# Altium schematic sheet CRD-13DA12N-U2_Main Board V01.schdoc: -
size 558 x 431 mm; ENG_APP_DATE: --/--/--; DSN_APP_DATE: --/--/--; CHK_APP_DATE: --/--/--; Date: -; Revision: -; SheetNumber: 1; SheetTotal: 1
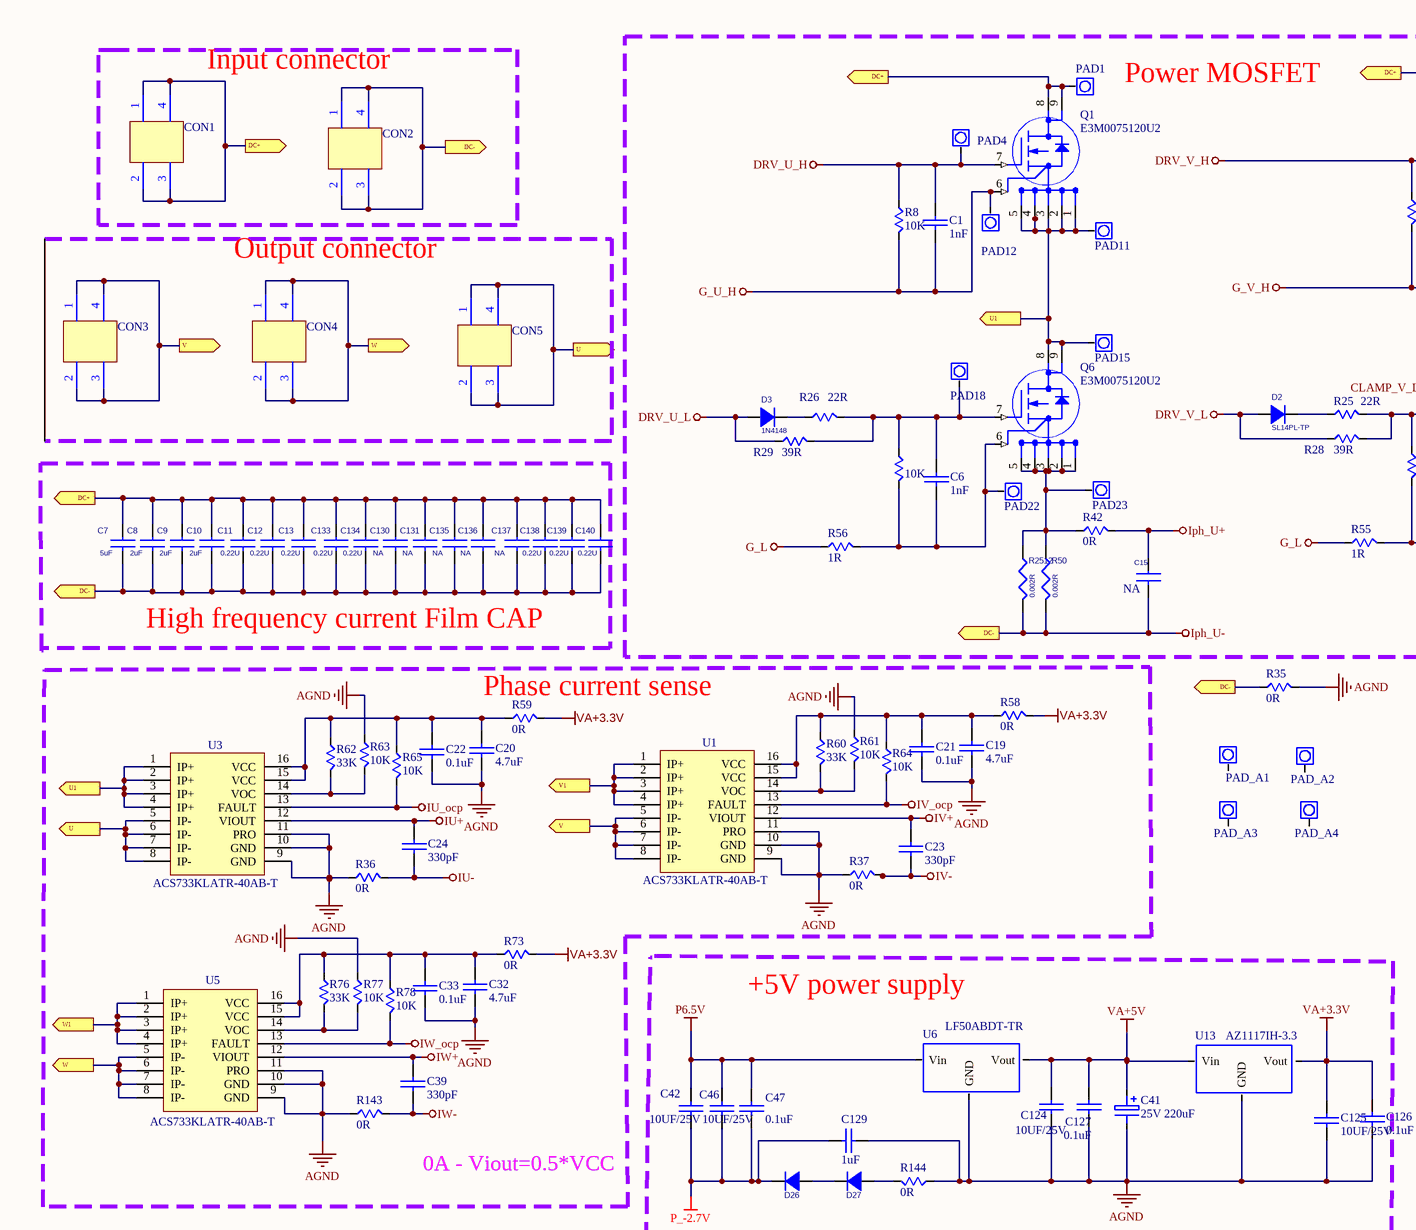
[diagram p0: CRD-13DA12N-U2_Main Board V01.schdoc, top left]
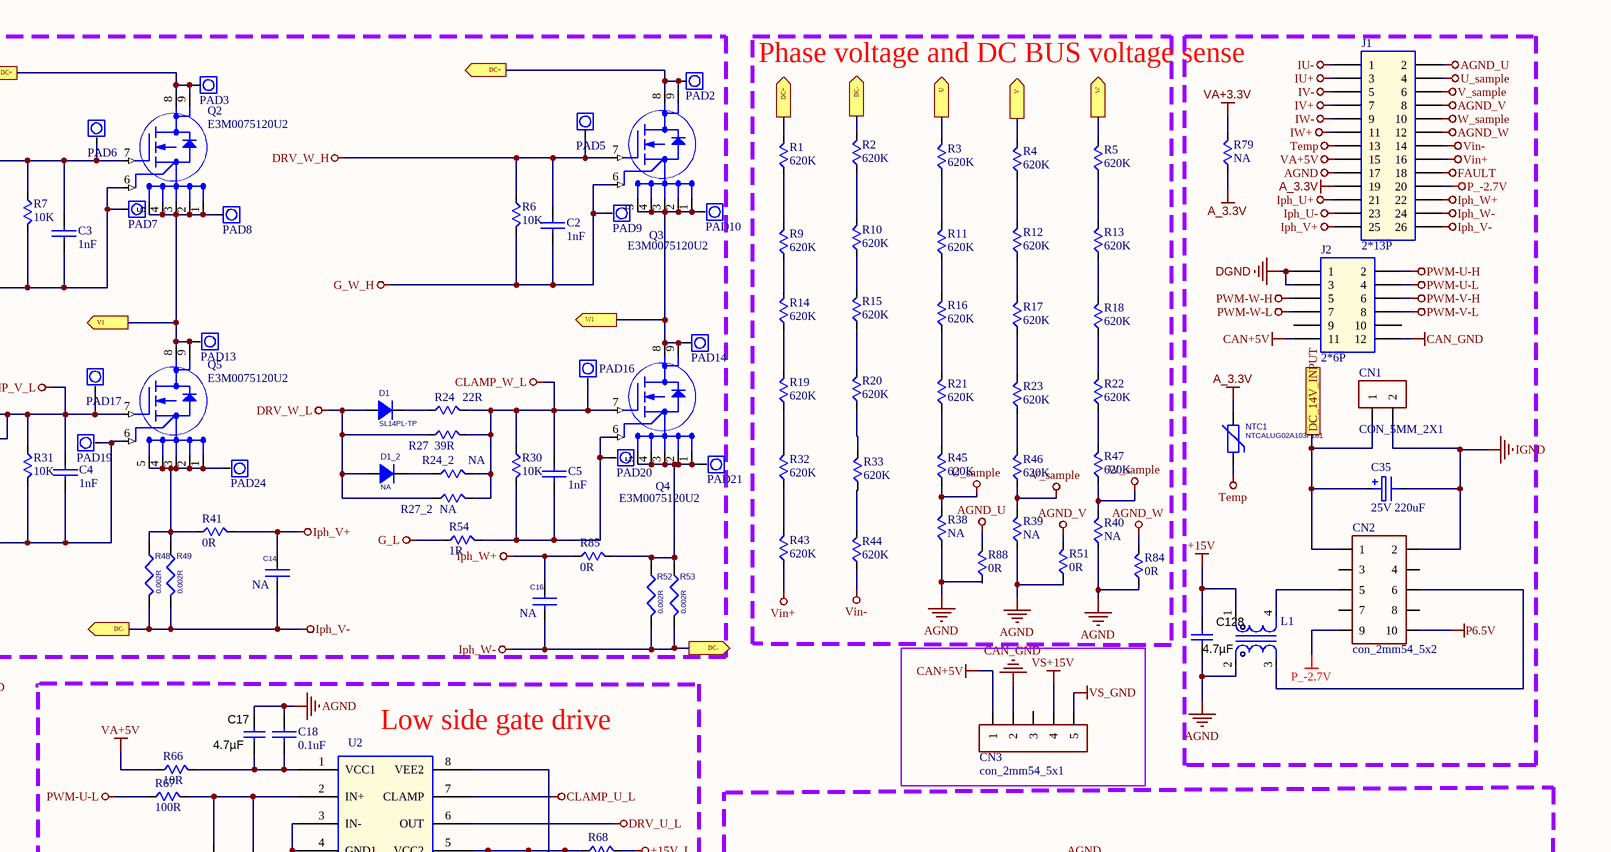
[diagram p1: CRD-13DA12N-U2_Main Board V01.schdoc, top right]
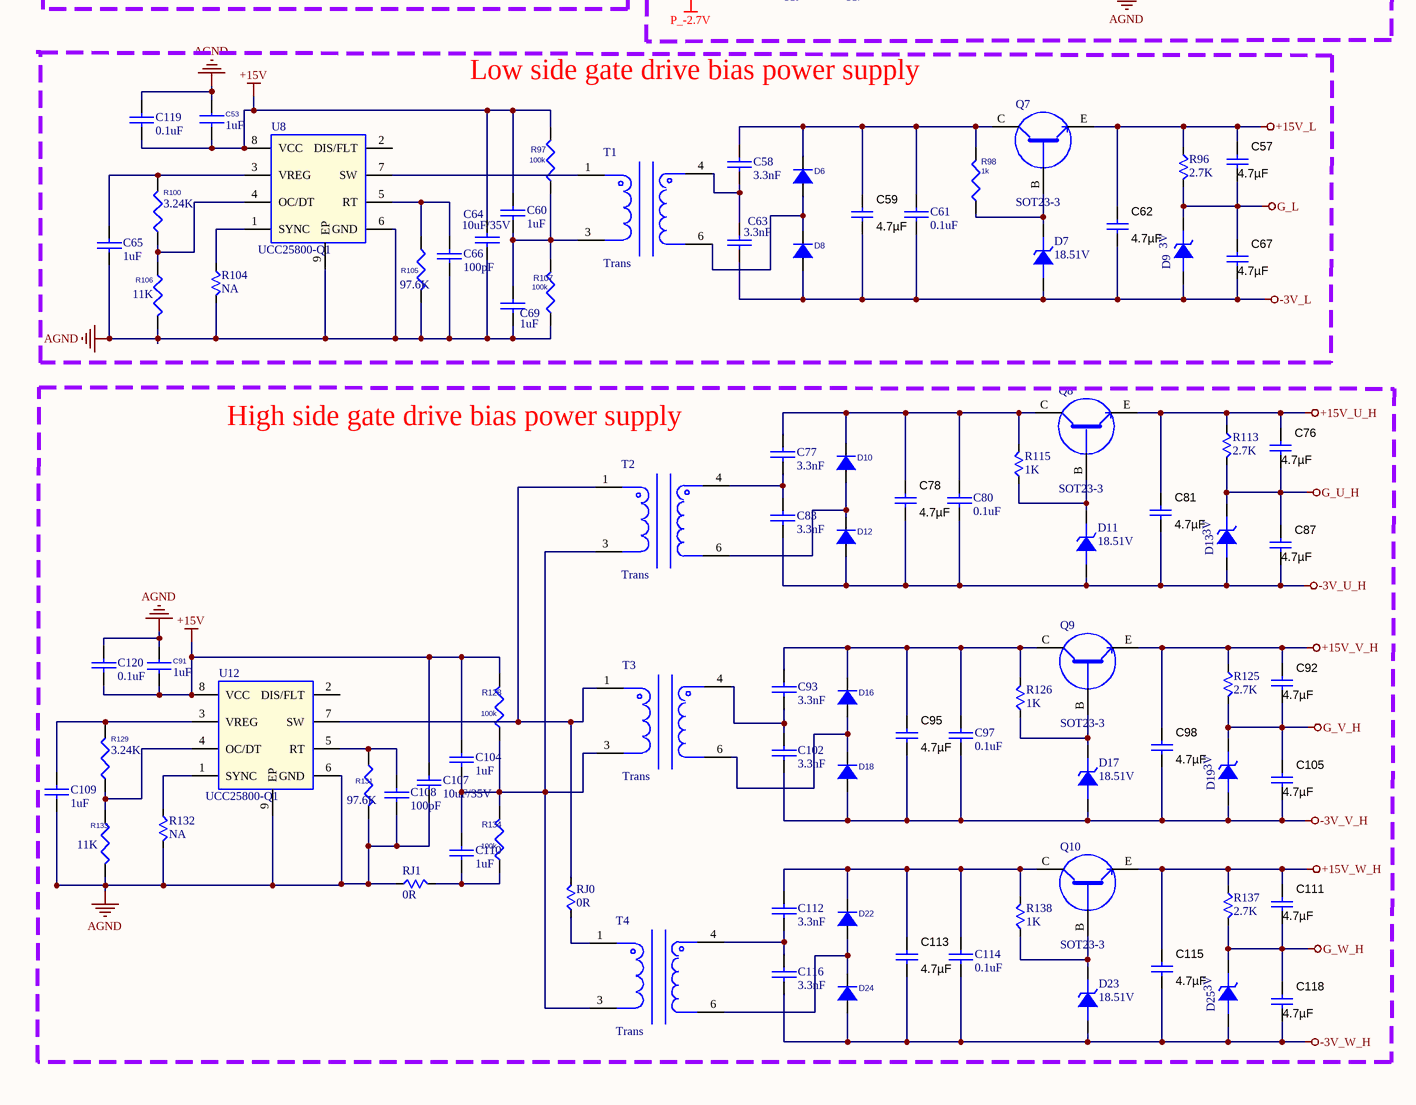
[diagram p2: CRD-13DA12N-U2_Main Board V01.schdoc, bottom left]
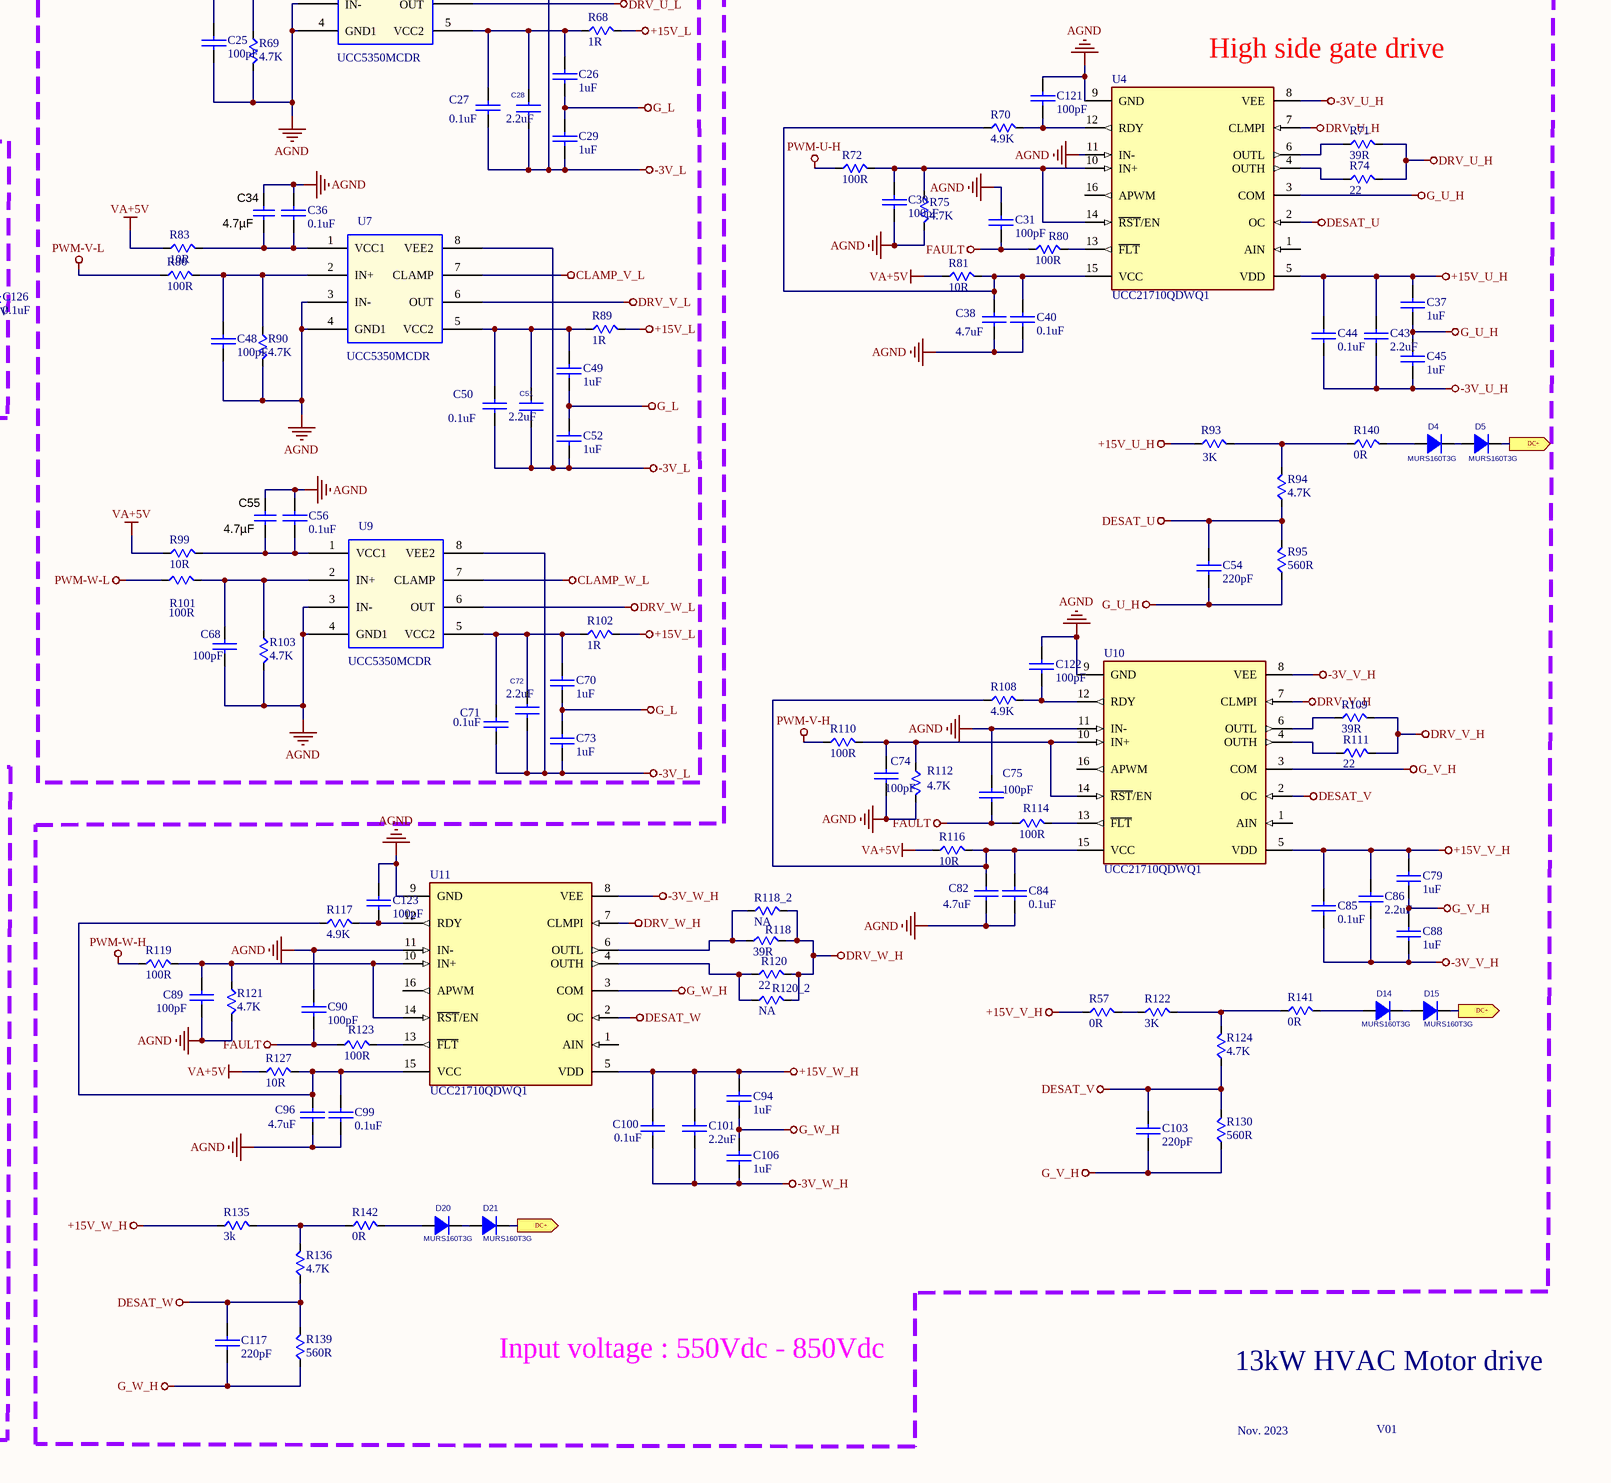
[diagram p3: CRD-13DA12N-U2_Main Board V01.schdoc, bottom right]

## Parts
C1  1nF  [C0603]
C2  1nF  [C0603]
C3  1nF  [C0603]
C4  1nF  [C0603]
C5  1nF  [C0603]
C6  1nF  [C0603]
C7  5uF  [capfilm_31_5x18_5mm]
C8  2uF  [capfilm_31_5x12_5mm]
C9  2uF  [capfilm_31_5x12_5mm]
C10  2uF  [capfilm_31_5x12_5mm]
C11  0.22U  [C2220]
C12  0.22U  [C2220]
C13  0.22U  [C2220]
C14  NA  [0402]
C15  NA  [0402]
C16  NA  [0402]
C17  ValueDisplayed: 4.7µF  [C0603]  (hidden comment: GRT21BR61H475KE13L)
C18  0.1uF  [C0603]
C19  4.7uF  [C0603]
C20  4.7uF  [C0603]
C21  0.1uF  [C0603]
C22  0.1uF  [C0603]
C23  330pF  [C0603]
C24  330pF  [C0603]
C25  100pF  [C0603]
C26  1uF  [C0603]
C27  0.1uF  [C0603]
C28  2.2uF  [C0603]
C29  1uF  [C0603]
C30  100pF  [C0603]
C31  100pF  [C0603]
C32  4.7uF  [C0603]
C33  0.1uF  [C0603]
C34  ValueDisplayed: 4.7µF  [C0603]  (hidden comment: GRT21BR61H475KE13L)
C35  25V 220uF  [ecap_d8p3_5]
C36  0.1uF  [C0603]
C37  1uF  [C0603]
C38  4.7uF  [C0603]
C39  330pF  [C0603]
C40  0.1uF  [C0603]
C41  25V 220uF  [ecap_d8p3_5]
C42  10UF/25V  [C1206]
C43  2.2uF  [C0603]
C44  0.1uF  [C0603]
C45  1uF  [C0603]
C46  10UF/25V  [C1206]
C47  0.1uF  [C0603]
C48  100pF  [C0603]
C49  1uF  [C0603]
C50  0.1uF  [C0603]
C51  2.2uF  [C0603]
C52  1uF  [C0603]
C53  1uF  [C0603]
C54  220pF  [C0603]
C55  ValueDisplayed: 4.7µF  [C0603]  (hidden comment: GRT21BR61H475KE13L)
C56  0.1uF  [C0603]
C57  ValueDisplayed: 4.7µF  [0805_HV]  (hidden comment: GRT21BR61H475KE13L)
C58  3.3nF  [C0805]
C59  ValueDisplayed: 4.7µF  [0805_HV]  (hidden comment: GRT21BR61H475KE13L)
C60  1uF  [C0603]
C61  0.1uF  [C0603]
C62  ValueDisplayed: 4.7µF  [0805_HV]  (hidden comment: GRT21BR61H475KE13L)
C63  3.3nF  [C0805]
C64  10uF/35V  [C1206]
C65  1uF  [C0603]
C66  100pF  [C0603]
C67  ValueDisplayed: 4.7µF  [C0603]  (hidden comment: GRT21BR61H475KE13L)
C68  100pF  [C0603]
C69  1uF  [C0603]
C70  1uF  [C0603]
C71  0.1uF  [C0603]
C72  2.2uF  [C0603]
C73  1uF  [C0603]
C74  100pF  [C0603]
C75  100pF  [C0603]
C76  ValueDisplayed: 4.7µF  [0805_HV]  (hidden comment: GRT21BR61H475KE13L)
C77  3.3nF  [C0805]
C78  ValueDisplayed: 4.7µF  [0805_HV]  (hidden comment: GRT21BR61H475KE13L)
C79  1uF  [C0603]
C80  0.1uF  [C0603]
C81  ValueDisplayed: 4.7µF  [0805_HV]  (hidden comment: GRT21BR61H475KE13L)
C82  4.7uF  [C0603]
C83  3.3nF  [C0805]
C84  0.1uF  [C0603]
C85  0.1uF  [C0603]
C86  2.2uF  [C0603]
C87  ValueDisplayed: 4.7µF  [C0603]  (hidden comment: GRT21BR61H475KE13L)
C88  1uF  [C0603]
C89  100pF  [C0603]
C90  100pF  [C0603]
C91  1uF  [C0603]
C92  ValueDisplayed: 4.7µF  [0805_HV]  (hidden comment: GRT21BR61H475KE13L)
C93  3.3nF  [C0805]
C94  1uF  [C0603]
C95  ValueDisplayed: 4.7µF  [0805_HV]  (hidden comment: GRT21BR61H475KE13L)
C96  4.7uF  [C0603]
C97  0.1uF  [C0603]
C98  ValueDisplayed: 4.7µF  [0805_HV]  (hidden comment: GRT21BR61H475KE13L)
C99  0.1uF  [C0603]
C100  0.1uF  [C0603]
C101  2.2uF  [C0603]
C102  3.3nF  [C0805]
C103  220pF  [C0603]
C104  1uF  [C0603]
C105  ValueDisplayed: 4.7µF  [C0603]  (hidden comment: GRT21BR61H475KE13L)
C106  1uF  [C0603]
C107  10uF/35V  [C1206]
C108  100pF  [C0603]
C109  1uF  [C0603]
C110  1uF  [C0603]
C111  ValueDisplayed: 4.7µF  [0805_HV]  (hidden comment: GRT21BR61H475KE13L)
C112  3.3nF  [C0805]
C113  ValueDisplayed: 4.7µF  [0805_HV]  (hidden comment: GRT21BR61H475KE13L)
C114  0.1uF  [C0603]
C115  ValueDisplayed: 4.7µF  [0805_HV]  (hidden comment: GRT21BR61H475KE13L)
C116  3.3nF  [C0805]
C117  220pF  [C0603]
C118  ValueDisplayed: 4.7µF  [C0603]  (hidden comment: GRT21BR61H475KE13L)
C119  0.1uF  [C0603]
C120  0.1uF  [C0603]
C121  100pF  [C0603]
C122  100pF  [C0603]
C123  100pF  [C0603]
C124  10UF/25V  [C1206]
C125  10UF/25V  [C1206]
C126  0.1uF  [C0603]
C127  0.1uF  [C0603]
C128  ValueDisplayed: 4.7µF  [0805_HV]  (hidden comment: GRT21BR61H475KE13L)
C129  1uF  [C0603]
C130  NA  [C2220]
C131  NA  [C2220]
C133  0.22U  [C2220]
C134  0.22U  [C2220]
C135  NA  [C2220]
C136  NA  [C2220]
C137  NA  [C2220]
C138  0.22U  [C2220]
C139  0.22U  [C2220]
C140  0.22U  [C2220]
CN1  CON_5MM_2X1  [CON_5MM_2X1]
CN2  con_2mm54_5x2  [con_2mm54_5x2]
CN3  con_2mm54_5x1  [con_2mm54_5x1]
CON1  CON  [CON4_500X720-800X800]  (value not drawn)
CON2  CON  [CON4_500X720-800X800]  (value not drawn)
CON3  CON  [CON4_500X720-800X800]  (value not drawn)
CON4  CON  [CON4_500X720-800X800]  (value not drawn)
CON5  CON  [CON4_500X720-800X800]  (value not drawn)
D1  SL14PL-TP  [SOD-123]
D1_2  NA  [SOD-123]
D2  SL14PL-TP  [SOD-123]
D3  1N4148  [SOD-123]
D4  MURS160T3G  [SMB]
D5  MURS160T3G  [SMB]
D6  PMEG6010CEGWJ  [SOD-123]  (value not drawn)
D7  18.51V  [SOD323F]
D8  PMEG6010CEGWJ  [SOD-123]  (value not drawn)
D9  3V  [SMDSOD123]
D10  PMEG6010CEGWJ  [SMDSOD123]  (value not drawn)
D11  18.51V  [SOD323F]
D12  PMEG6010CEGWJ  [SMDSOD123]  (value not drawn)
D13  3V  [SMDSOD123]
D14  MURS160T3G  [SMB]
D15  MURS160T3G  [SMB]
D16  PMEG6010CEGWJ  [SMDSOD123]  (value not drawn)
D17  18.51V  [SOD323F]
D18  PMEG6010CEGWJ  [SMDSOD123]  (value not drawn)
D19  3V  [SMDSOD123]
D20  MURS160T3G  [SMB]
D21  MURS160T3G  [SMB]
D22  PMEG6010CEGWJ  [SMDSOD123]  (value not drawn)
D23  18.51V  [SOD323F]
D24  PMEG6010CEGWJ  [SMDSOD123]  (value not drawn)
D25  3V  [SMDSOD123]
D26  PMEG6010CEGWJ  [SMA]  (value not drawn)
D27  PMEG6010CEGWJ  [SMA]  (value not drawn)
J1  2*13P  [HDR2X13H-254MM-F]
J2  2*6P  [HDR2X6H-254MM-F]
L1  L4_550X1050-900X1600  [L4_550X1050-900X1600]  (value not drawn)
NTC1  NTCALUG02A103F161  [NTC2_54]
PAD1  PAD  [TEST_270X100_SMT]  (value not drawn)
PAD2  PAD  [TEST_270X100_SMT]  (value not drawn)
PAD3  PAD  [TEST_270X100_SMT]  (value not drawn)
PAD4  PAD  [TEST_270X100_SMT]  (value not drawn)
PAD5  PAD  [TEST_270X100_SMT]  (value not drawn)
PAD6  PAD  [TEST_270X100_SMT]  (value not drawn)
PAD7  PAD  [TEST_270X100_SMT]  (value not drawn)
PAD8  PAD  [TEST_270X100_SMT]  (value not drawn)
PAD9  PAD  [TEST_270X100_SMT]  (value not drawn)
PAD10  PAD  [TEST_270X100_SMT]  (value not drawn)
PAD11  PAD  [TEST_270X100_SMT]  (value not drawn)
PAD12  PAD  [TEST_270X100_SMT]  (value not drawn)
PAD13  PAD  [TEST_270X100_SMT]  (value not drawn)
PAD14  PAD  [TEST_270X100_SMT]  (value not drawn)
PAD15  PAD  [TEST_270X100_SMT]  (value not drawn)
PAD16  PAD  [TEST_270X100_SMT]  (value not drawn)
PAD17  PAD  [TEST_270X100_SMT]  (value not drawn)
PAD18  PAD  [TEST_270X100_SMT]  (value not drawn)
PAD19  PAD  [TEST_270X100_SMT]  (value not drawn)
PAD20  PAD  [TEST_270X100_SMT]  (value not drawn)
PAD21  PAD  [TEST_270X100_SMT]  (value not drawn)
PAD22  PAD  [TEST_270X100_SMT]  (value not drawn)
PAD23  PAD  [TEST_270X100_SMT]  (value not drawn)
PAD24  PAD  [TEST_270X100_SMT]  (value not drawn)
PAD_A1  PAD  [NTH122]  (value not drawn)
PAD_A2  PAD  [NTH122]  (value not drawn)
PAD_A3  PAD  [NTH122]  (value not drawn)
PAD_A4  PAD  [NTH122]  (value not drawn)
Q1  E3M0075120U2  [TSC_U2]
Q2  E3M0075120U2  [TSC_U2]
Q3  E3M0075120U2  [TSC_U2]
Q4  E3M0075120U2  [TSC_U2]
Q5  E3M0075120U2  [TSC_U2]
Q6  E3M0075120U2  [TSC_U2]
Q7  SOT23-3  [SOT-23-BCE]
Q8  SOT23-3  [SOT-23-BCE]
Q9  SOT23-3  [SOT-23-BCE]
Q10  SOT23-3  [SOT-23-BCE]
R1  620K  [R1206]
R2  620K  [R1206]
R3  620K  [R1206]
R4  620K  [R1206]
R5  620K  [R1206]
R6  10K  [R0603]
R7  10K  [R0603]
R8  10K  [R0603]
R9  620K  [R1206]
R10  620K  [R1206]
R11  620K  [R1206]
R12  620K  [R1206]
R13  620K  [R1206]
R14  620K  [R1206]
R15  620K  [R1206]
R16  620K  [R1206]
R17  620K  [R1206]
R18  620K  [R1206]
R19  620K  [R1206]
R20  620K  [R1206]
R21  620K  [R1206]
R22  620K  [R1206]
R23  620K  [R1206]
R24  22R  [R1206]
R24_2  NA  [R1206]
R25  22R  [R1206]
R26  22R  [R1206]
R27  39R  [R1206]
R27_2  NA  [R1206]
R28  39R  [R1206]
R29  39R  [R1206]
R30  10K  [R0603]
R31  10K  [R0603]
R32  620K  [R1206]
R33  620K  [R1206]
R34  10K  [R0603]
R35  0R  [R0603]
R36  0R  [R0603]
R37  0R  [R0603]
R38  NA  [R1206]
R39  NA  [R1206]
R40  NA  [R1206]
R41  0R  [R0603]
R42  0R  [R0603]
R43  620K  [R1206]
R44  620K  [R1206]
R45  620K  [R1206]
R46  620K  [R1206]
R47  620K  [R1206]
R48  0.002R  [R2512]
R49  0.002R  [R2512]
R50  0.002R  [R2512]
R51  0R  [R0603]
R52  0.002R  [R2512]
R53  0.002R  [R2512]
R54  1R  [R1206]
R55  1R  [R1206]
R56  1R  [R1206]
R57  0R  [R0603]
R58  0R  [R0603]
R59  0R  [R0603]
R60  33K  [R0603]
R61  10K  [R0603]
R62  33K  [R0603]
R63  10K  [R0603]
R64  10K  [R0603]
R65  10K  [R0603]
R66  10R  [R0603]
R67  100R  [R0603]
R68  1R  [R1206]
R69  4.7K  [R0603]
R70  4.9K  [R0603]
R71  39R  [R1206]
R72  100R  [R0603]
R73  0R  [R0603]
R74  22  [R1206]
R75  4.7K  [R0603]
R76  33K  [R0603]
R77  10K  [R0603]
R78  10K  [R0603]
R79  NA  [R0805]
R80  100R  [R0603]
R81  10R  [R0603]
R83  10R  [R0603]
R84  0R  [R0603]
R85  0R  [R0603]
R86  100R  [R1206]
R88  0R  [R0603]
R89  1R  [R1206]
R90  4.7K  [R0603]
R93  3K  [R0805]
R94  4.7K  [R0603]
R95  560R  [R0603]
R96  2.7K  [R0603]
R97  100k  [R0603]
R98  1k  [R1206]
R99  10R  [R0603]
R100  3.24K  [R0603]
R101  100R  [R0603]
R102  1R  [R1206]
R103  4.7K  [R0603]
R104  NA  [R0603]
R105  97.6K  [R0603]
R106  11K  [R0603]
R107  100k  [R0603]
R108  4.9K  [R0603]
R109  39R  [R1206]
R110  100R  [R0603]
R111  22  [R1206]
R112  4.7K  [R0603]
R113  2.7K  [R0603]
R114  100R  [R0603]
R115  1K  [R0603]
R116  10R  [R0603]
R117  4.9K  [R0603]
R118  39R  [R1206]
R118_2  NA  [R1206]
R119  100R  [R0603]
R120  22  [R1206]
R120_2  NA  [R1206]
R121  4.7K  [R0603]
R122  3K  [R0805]
R123  100R  [R0603]
R124  4.7K  [R0603]
R125  2.7K  [R0603]
R126  1K  [R0603]
R127  10R  [R0603]
R128  100k  [R0603]
R129  3.24K  [R0603]
R130  560R  [R0603]
R131  97.6K  [R0603]
R132  NA  [R0603]
R133  11K  [R0603]
R134  100k  [R0603]
R135  3k  [R0805]
R136  4.7K  [R0603]
R137  2.7K  [R0603]
R138  1K  [R0603]
R139  560R  [R0603]
R140  0R  [R0603]
R141  0R  [R0603]
R142  0R  [R0603]
R143  0R  [R0603]
R144  0R  [R1206]
R2512  0.002R  [R2512]
RJ0  0R  [R1206]
RJ1  0R  [R1206]
T1  Trans  [T4_700X850X600]
T2  Trans  [T4_700X850X600]
T3  Trans  [T4_700X850X600]
T4  Trans  [T4_700X850X600]
U1  ACS733KLATR-40AB-T  [SOP16_127-1063X1050]
U2  UCC5350MCDR  [SOIC-8]
U3  ACS733KLATR-40AB-T  [SOP16_127-1063X1050]
U4  UCC21710QDWQ1  [FP-DW0016B-IPC_B]
U5  ACS733KLATR-40AB-T  [SOP16_127-1063X1050]
U6  LF50ABDT-TR  [TO252AB]
U7  UCC5350MCDR  [SOIC-8]
U8  UCC25800-Q1  [SOP8_065-505X310-HS185X215]
U9  UCC5350MCDR  [SOIC-8]
U10  UCC21710QDWQ1  [FP-DW0016B-IPC_B]
U11  UCC21710QDWQ1  [FP-DW0016B-IPC_B]
U12  UCC25800-Q1  [SOP8_065-505X310-HS185X215]
U13  AZ1117IH-3.3  [SOT223]

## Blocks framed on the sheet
Input connector: CON1 CON2
Power MOSFET: C1-C6 C14-C16 D1 D1_2 D2 D3 PAD1-PAD24 Q1-Q6 R6-R8 R24 R24_2 R25-R27 R27_2 R28-R31 R34 R41 R42 R48-R50 R52-R56 R85 R2512
Phase voltage and DC BUS voltage sense: R1-R5 R9-R23 R32 R33 R38-R40 R43-R47 R51 R84 R88
Output connector: CON3-CON5
Phase current sense: C19-C24 C32 C33 C39 R36 R37 R58-R65 R73 R76-R78 R143 U1 U3 U5
High side gate drive bias power supply: C76-C78 C80 C81 C83 C87 C91-C93 C95 C97 C98 C102 C104 C105 C107-C116 C118 C120 D10-D13 D16-D19 D22-D25 Q8-Q10 R113 R115 R125 R126 R128 R129 R131-R134 R137 R138 RJ0 RJ1 T2-T4 U12

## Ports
DC+ (out), DC- (out), DC_14V_INPUT, U1 (out), U (out), V1 (out), V (out), W1 (out), W (out)

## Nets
+15V: C53.2 C60.1 C64.1 C91.2 C104.1 C107.1 C119.2 C120.2 C128.1 L1.1 R97.2 R128.2 U8.8(VCC) U12.8(VCC)
+15V_L: C57.1 C62.1 Q7.E R68.2 R89.2 R96.1 R102.2
+15V_U_H: C37.1 C43.1 C44.1 C76.1 C81.1 Q8.E R93.1 R113.1 U4.5(VDD)
+15V_V_H: C79.1 C85.1 C86.1 C92.1 C98.1 Q9.E R57.1 R125.1 U10.5(VDD)
+15V_W_H: C94.1 C100.1 C101.1 C111.1 C115.1 Q10.E R135.1 R137.1 U11.5(VDD)
-3V_L: C27.2 C28.2 C29.2 C50.2 C51.2 C52.2 C59.2 C61.2 C62.2 C63.2 C67.2 C71.2 C72.2 C73.2 D7.1(ANODE) D8.1(A) D9.1(ANODE) U2.8(VEE2) U7.8(VEE2) U9.8(VEE2)
-3V_U_H: C43.2 C44.2 C45.2 C78.2 C80.2 C81.2 C83.2 C87.2 D11.1(ANODE) D12.1(A) D13.1(ANODE) U4.8(VEE)
-3V_V_H: C85.2 C86.2 C88.2 C95.2 C97.2 C98.2 C102.2 C105.2 D17.1(ANODE) D18.1(A) D19.1(ANODE) U10.8(VEE)
-3V_W_H: C100.2 C101.2 C106.2 C113.2 C114.2 C115.2 C116.2 C118.2 D23.1(ANODE) D24.1(A) D25.1(ANODE) U11.8(VEE)
A_3.3V: J1.19 NTC1.1 R79.1
AGND: C17.1 C18.1 C19.2 C20.2 C21.2 C22.2 C25.2 C30.2 C31.1 C32.2 C33.2 C34.1 C36.1 C38.2 C40.2 C41.2 C48.2 C53.1 C55.1 C56.1 C64.2 C65.2 C66.2 C68.2 C69.2 C74.2 C75.1 C82.2 C84.2 C89.2 C90.1 C91.1 C96.2 C99.2 C107.2 C108.2 C109.2 C119.1 C120.1 C121.1 C122.1 C123.1 C124.2 C125.2 C126.2 C127.2 C128.2 C129.2 J1.17 L1.2 R35.2 R36.1 R37.1 R38.1 R39.1 R40.1 R51.1 R61.1 R63.1 R69.2 R75.2 R77.1 R84.1 R88.1 R90.2 R103.2 R104.2 R105.2 R106.2 R107.1 R112.2 R121.2 R131.2 R132.2 R133.2 R143.1 R144.1 RJ1.1 U1.9(GND) U1.10(GND) U1.11(PRO) U2.3(IN-) U2.4(GND1) U3.9(GND) U3.10(GND) U3.11(PRO) U4.9(GND) U4.11(IN-) U5.9(GND) U5.10(GND) U5.11(PRO) U6.2(GND) U7.3(IN-) U7.4(GND1) U8.6(GND) U8.9(EP) U9.3(IN-) U9.4(GND1) U10.9(GND) U10.11(IN-) U11.9(GND) U11.11(IN-) U12.6(GND) U12.9(EP) U13.1(GND)
AGND_U: J1.2 R88.2
AGND_V: J1.8 R51.2
AGND_W: J1.12 R84.2
CAN+5V: CN3.1 J2.11
CAN_GND: CN3.2 J2.12
CLAMP_U_L: U2.7(CLAMP)
CLAMP_V_L: C4.1 PAD17.1 Q5.7(GATE) R25.2 R28.2 R31.1 U7.7(CLAMP)
CLAMP_W_L: C5.1 PAD16.1 Q4.7(GATE) R24.2 R24_2.2 R27.2 R27_2.2 R30.1 U9.7(CLAMP)
DESAT_U: C54.1 R94.1 R95.2 U4.2(OC)
DESAT_V: C103.1 R124.1 R130.2 U10.2(OC)
DESAT_W: C117.1 R136.1 R139.2 U11.2(OC)
DGND: J2.1 J2.3
DRV_U_H: C1.1 PAD4.1 Q1.7(GATE) R8.1 R71.2 R74.2 U4.7(CLMPI)
DRV_U_L: D3.1(A) R29.1 U2.6(OUT)
DRV_V_H: C3.1 PAD6.1 Q2.7(GATE) R7.1 R109.2 R111.2 U10.7(CLMPI)
DRV_V_L: D2.1(A) R28.1 U7.6(OUT)
DRV_W_H: C2.1 PAD5.1 Q3.7(GATE) R6.1 R118.2 R118_2.2 R120.2 R120_2.2 U11.7(CLMPI)
DRV_W_L: D1.1(A) D1_2.1(A) R27.1 R27_2.1 U9.6(OUT)
FAULT: C31.2 C75.2 C90.2 J1.18 R80.1 R114.1 R123.1
G_L: C26.2 C29.1 C49.2 C52.1 C57.2 C67.1 C70.2 C73.1 D9.2(CATHODE) R54.1 R55.1 R56.1 R96.2
G_U_H: C1.2 C37.2 C45.1 C54.2 C76.2 C87.1 D13.2(CATHODE) PAD12.1 Q1.6(GATE_RTN) R8.2 R95.1 R113.2 U4.3(COM)
G_V_H: C3.2 C79.2 C88.1 C92.2 C103.2 C105.1 D19.2(CATHODE) PAD7.1 Q2.6(GATE_RTN) R7.2 R125.2 R130.1 U10.3(COM)
G_W_H: C2.2 C94.2 C106.1 C111.2 C117.2 C118.1 D25.2(CATHODE) PAD9.1 Q3.6(GATE_RTN) R6.2 R137.2 R139.1 U11.3(COM)
IGND: C35.2 CN1.2 CN2.2
Iph_U+: C15.1 J1.21 R42.2
Iph_U-: C7.2 C8.2 C9.2 C10.2 C11.2 C12.2 C13.2 C14.2 C15.2 C16.2 C130.2 C131.2 C133.2 C134.2 C135.2 C136.2 C137.2 C138.2 C139.2 C140.2 CON2.1 CON2.2 CON2.3 CON2.4 J1.23 J1.24 J1.26 R2.2 R35.1 R48.2 R49.2 R50.2 R52.2 R53.2 R2512.2 ; port DC-  [also labelled Iph_V-, Iph_W-]
Iph_V+: C14.1 J1.25 R41.2
Iph_W+: C16.1 J1.22 R85.1
IU+: C24.1 J1.3 U3.12(VIOUT)
IU-: C24.2 J1.1 R36.2
IU_ocp: R65.2 U3.13(FAULT)
IV+: C23.1 J1.7 U1.12(VIOUT)
IV-: C23.2 J1.5 R37.2
IV_ocp: R64.2 U1.13(FAULT)
IW+: C39.1 J1.11 U5.12(VIOUT)
IW-: C39.2 J1.9 R143.2
IW_ocp: R78.2 U5.13(FAULT)
P6.5V: C42.1 C46.1 C47.1 CN2.10 U6.3(Vin)
P_-2.7V: C42.2 C46.2 C47.2 C129.1 CN2.9 D26.2(K) J1.20
PWM-U-H: J2.2 R72.1
PWM-U-L: J2.4 R67.1
PWM-V-H: J2.6 R110.1
PWM-V-L: J2.8 R86.1
PWM-W-H: J2.5 R119.1
PWM-W-L: J2.7 R101.1
Temp: J1.13 NTC1.2
U_sample: J1.4 R38.2 R45.1
V_sample: J1.6 R39.2 R46.1
VA+3.3V: C125.1 C126.1 R58.2 R59.2 R73.2 R79.2 U13.2(Vout)
VA+5V: C41.1 C124.1 C127.1 J1.15 R66.1 R81.1 R83.1 R99.1 R116.1 R127.1 U6.1(Vout) U13.3(Vin)
Vin+: J1.16 R43.1
Vin-: J1.14 R44.1
VS+15V: CN3.4
VS_GND: CN3.5
W_sample: J1.10 R40.2 R47.1
DC+: C7.1 C8.1 C9.1 C10.1 C11.1 C12.1 C13.1 C130.1 C131.1 C133.1 C134.1 C135.1 C136.1 C137.1 C138.1 C139.1 C140.1 CON1.1 CON1.2 CON1.3 CON1.4 D5.2(K) D15.2(K) D21.2(K) PAD1.1 PAD2.1 PAD3.1 Q1.8(DRAIN) Q1.9(DRAIN) Q2.8(DRAIN) Q2.9(DRAIN) Q3.8(DRAIN) Q3.9(DRAIN) R1.2 ; port DC+
DC_14V_INPUT: C35.1 CN1.1 CN2.1 ; port DC_14V_INPUT
U: CON5.1 CON5.2 CON5.3 CON5.4 R3.2 U3.5(IP-) U3.6(IP-) U3.7(IP-) U3.8(IP-) ; port U
U1: PAD11.1 PAD15.1 Q1.1(SOURCE1) Q1.2(SOURCE1) Q1.3(SOURCE1) Q1.4(SOURCE1) Q1.5(SOURCE1) Q6.8(DRAIN) Q6.9(DRAIN) U3.1(IP+) U3.2(IP+) U3.3(IP+) U3.4(IP+) ; port U1
V: CON3.1 CON3.2 CON3.3 CON3.4 R4.2 U1.5(IP-) U1.6(IP-) U1.7(IP-) U1.8(IP-) ; port V
V1: PAD8.1 PAD13.1 Q2.1(SOURCE1) Q2.2(SOURCE1) Q2.3(SOURCE1) Q2.4(SOURCE1) Q2.5(SOURCE1) Q5.8(DRAIN) Q5.9(DRAIN) U1.1(IP+) U1.2(IP+) U1.3(IP+) U1.4(IP+) ; port V1
W: CON4.1 CON4.2 CON4.3 CON4.4 R5.2 U5.5(IP-) U5.6(IP-) U5.7(IP-) U5.8(IP-) ; port W
W1: PAD10.1 PAD14.1 Q3.1(SOURCE1) Q3.2(SOURCE1) Q3.3(SOURCE1) Q3.4(SOURCE1) Q3.5(SOURCE1) Q4.8(DRAIN) Q4.9(DRAIN) U5.1(IP+) U5.2(IP+) U5.3(IP+) U5.4(IP+) ; port W1
NetC4_2: C4.2 PAD19.1 Q5.6(GATE_RTN) R31.2 R55.2
NetC5_2: C5.2 PAD20.1 Q4.6(GATE_RTN) R30.2 R54.2
NetC6_1: C6.1 PAD18.1 Q6.7(GATE) R26.2 R29.2 R34.1
NetC6_2: C6.2 PAD22.1 Q6.6(GATE_RTN) R34.2 R56.2
NetC17_2: C17.2 C18.2 R66.2 U2.1(VCC1)
NetC19_1: C19.1 C21.1 R58.1 R60.1 R64.1 U1.15(VCC) U1.16(VCC)
NetC20_1: C20.1 C22.1 R59.1 R62.1 R65.1 U3.15(VCC) U3.16(VCC)
NetC25_1: C25.1 R67.2 R69.1 U2.2(IN+)
NetC26_1: C26.1 C27.1 C28.1 R68.1 U2.5(VCC2)
NetC30_1: C30.1 R72.2 R75.1 U4.10(IN+) U4.14(~{RST}/EN)
NetC32_1: C32.1 C33.1 R73.1 R76.1 R78.1 U5.15(VCC) U5.16(VCC)
NetC34_2: C34.2 C36.2 R83.2 U7.1(VCC1)
NetC38_1: C38.1 C40.1 R70.1 R81.2 U4.15(VCC)
NetC48_1: C48.1 R86.2 R90.1 U7.2(IN+)
NetC49_1: C49.1 C50.1 C51.1 R89.1 U7.5(VCC2)
NetC55_2: C55.2 C56.2 R99.2 U9.1(VCC1)
NetC58_1: C58.1 C59.1 C61.1 D6.2(K) Q7.C R98.2
NetC58_2: C58.2 C63.1 T1.4
NetC60_2: C60.2 C69.1 R97.1 R107.2 T1.3
NetC65_1: C65.1 R100.2 U8.3(VREG)
NetC66_1: C66.1 R105.1 U8.5(RT)
NetC68_1: C68.1 R101.2 R103.1 U9.2(IN+)
NetC70_1: C70.1 C71.1 C72.1 R102.1 U9.5(VCC2)
NetC74_1: C74.1 R110.2 R112.1 U10.10(IN+) U10.14(~{RST}/EN)
NetC77_1: C77.1 C78.1 C80.1 D10.2(K) Q8.C R115.2
NetC77_2: C77.2 C83.1 T2.4
NetC82_1: C82.1 C84.1 R108.1 R116.2 U10.15(VCC)
NetC89_1: C89.1 R119.2 R121.1 U11.10(IN+) U11.14(~{RST}/EN)
NetC93_1: C93.1 C95.1 C97.1 D16.2(K) Q9.C R126.2
NetC93_2: C93.2 C102.1 T3.4
NetC96_1: C96.1 C99.1 R117.1 R127.2 U11.15(VCC)
NetC104_2: C104.2 C110.1 R128.1 R134.2 T2.3 T3.3 T4.3
NetC108_1: C108.1 R131.1 U12.5(RT)
NetC109_1: C109.1 R129.2 U12.3(VREG)
NetC110_2: C110.2 R134.1 RJ1.2
NetC112_1: C112.1 C113.1 C114.1 D22.2(K) Q10.C R138.2
NetC112_2: C112.2 C116.1 T4.4
NetC121_2: C121.2 R70.2 U4.12(RDY)
NetC122_2: C122.2 R108.2 U10.12(RDY)
NetC123_2: C123.2 R117.2 U11.12(RDY)
NetCN2_5: CN2.5 L1.4
NetCN2_6: CN2.6 L1.3
NetD1_2: D1.2(K) R24.1
NetD1_2_2: D1_2.2(K) R24_2.1
NetD2_2: D2.2(K) R25.1
NetD3_2: D3.2(K) R26.1
NetD4_1: D4.1(A) R140.2
NetD4_2: D4.2(K) D5.1(A)
NetD6_1: D6.1(A) D8.2(K) T1.6
NetD7_2: D7.2(CATHODE) Q7.B R98.1
NetD10_1: D10.1(A) D12.2(K) T2.6
NetD11_2: D11.2(CATHODE) Q8.B R115.1
NetD14_1: D14.1(A) R141.2
NetD14_2: D14.2(K) D15.1(A)
NetD16_1: D16.1(A) D18.2(K) T3.6
NetD17_2: D17.2(CATHODE) Q9.B R126.1
NetD20_1: D20.1(A) R142.2
NetD20_2: D20.2(K) D21.1(A)
NetD22_1: D22.1(A) D24.2(K) T4.6
NetD23_2: D23.2(CATHODE) Q10.B R138.1
NetD26_1: D26.1(A) D27.2(K)
NetD27_1: D27.1(A) R144.2
NetPAD21_1: PAD21.1 Q4.1(SOURCE1) Q4.2(SOURCE1) Q4.3(SOURCE1) Q4.4(SOURCE1) Q4.5(SOURCE1) R52.1 R53.1 R85.2
NetPAD23_1: PAD23.1 Q6.1(SOURCE1) Q6.2(SOURCE1) Q6.3(SOURCE1) Q6.4(SOURCE1) Q6.5(SOURCE1) R42.1 R50.1 R2512.1
NetPAD24_1: PAD24.1 Q5.1(SOURCE1) Q5.2(SOURCE1) Q5.3(SOURCE1) Q5.4(SOURCE1) Q5.5(SOURCE1) R41.1 R48.1 R49.1
NetR1_1: R1.1 R9.2
NetR2_1: R2.1 R10.2
NetR3_1: R3.1 R11.2
NetR4_1: R4.1 R12.2
NetR5_1: R5.1 R13.2
NetR9_1: R9.1 R14.2
NetR10_1: R10.1 R15.2
NetR11_1: R11.1 R16.2
NetR12_1: R12.1 R17.2
NetR13_1: R13.1 R18.2
NetR14_1: R14.1 R19.2
NetR15_1: R15.1 R20.2
NetR16_1: R16.1 R21.2
NetR17_1: R17.1 R23.2
NetR18_1: R18.1 R22.2
NetR19_1: R19.1 R32.2
NetR20_1: R20.1 R33.2
NetR21_1: R21.1 R45.2
NetR22_1: R22.1 R47.2
NetR23_1: R23.1 R46.2
NetR32_1: R32.1 R43.2
NetR33_1: R33.1 R44.2
NetR57_2: R57.2 R122.1
NetR60_2: R60.2 R61.2 U1.14(VOC)
NetR62_2: R62.2 R63.2 U3.14(VOC)
NetR71_1: R71.1 U4.6(OUTL)
NetR74_1: R74.1 U4.4(OUTH)
NetR76_2: R76.2 R77.2 U5.14(VOC)
NetR80_2: R80.2 U4.13(~{FLT})
NetR93_2: R93.2 R94.2 R140.1
NetR100_1: R100.1 R106.1 U8.4(OC/DT)
NetR104_1: R104.1 U8.1(SYNC)
NetR109_1: R109.1 U10.6(OUTL)
NetR111_1: R111.1 U10.4(OUTH)
NetR114_2: R114.2 U10.13(~{FLT})
NetR118_1: R118.1 R118_2.1 U11.6(OUTL)
NetR120_1: R120.1 R120_2.1 U11.4(OUTH)
NetR122_2: R122.2 R124.2 R141.1
NetR123_2: R123.2 U11.13(~{FLT})
NetR129_1: R129.1 R133.1 U12.4(OC/DT)
NetR132_1: R132.1 U12.1(SYNC)
NetR135_2: R135.2 R136.2 R142.1
NetRJ0_1: RJ0.1 T4.1
NetRJ0_2: RJ0.2 T2.1 T3.1 U12.7(SW)
NetT1_1: T1.1 U8.7(SW)

Not connected (* = marked no-connect by the designer): CN2 3 4 7 8; CN3 3; J2 9 10; PAD_A1 1; PAD_A2 1; PAD_A3 1; PAD_A4 1; U4 1(AIN) 16(APWM); U8 2(DIS/FLT); U10 1(AIN) 16(APWM); U11 1(AIN) 16(APWM); U12 2(DIS/FLT)

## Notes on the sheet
- High frequency current Film CAP
- (near U2) Low side gate drive
- (near U4) High side gate drive
- +5V power supply
- 0A - Viout=0.5*VCC
- Low side gate drive bias power supply
- Input voltage : 550Vdc - 850Vdc
- 13kW HVAC Motor drive
- Nov. 2023
- V01

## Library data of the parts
C1-C6 = C0603: CAP CER 1nF 50V X7R 0603; Manufacturer: Yageo; PN: CC0603KRX7R9BB102
C7 = CAP NP_Dup1: 5.0UF 10% 1100V FILM CAP MKP BOXED; Manufacturer: EPCOS; PCB Footprint: C0603; PN: B32774D0505K000
C8-C10 = CAP NP_Dup1: CAP FILM 2UF 10% 1.1KVDC RADIAL; Manufacturer: EPCOS; PCB Footprint: C0603; PN: B32774D0205K000
C11-C13 C133 C134 C138-C140 = CAP NP_Dup1: CAP CER 0.22UF 1KV X7R 2220; Manufacturer: Murata; PN: GRM55DR7LW224KW01K
C14-C16 = CAP NP: CAP CER 330PF 50V X7R 0402; Manufacturer: Yageo; PCB Footprint: C0603; PN: CC0402KRX7R9BB331
C17 C34 C55 C67 C87 C105 C118 = GRT21BR61H475KE13L: CAP CER 4.7UF 10V X7R 0603; Manufacturer: Marata; Polarized: N; CompType: Capacitor; U/M: EA; Cap_F: 0.0000047; Tolerance_%: 10; VDC_V: 50; Value2: 50V; TempCo: X5R; TaMin_C: -55; TaMax_C: 85; Cap_Case: 0805; SizeArea_mm2: 2.5; SizeAreaWB_mm2: 6.75; SizeX_mm: 2; SizeY_mm: 1.25; SizeZ_mm: 1.45; AEC Category: Q200; AEC Qualified: Y; AEC Grade: 3; PN: GRM188Z71A475KE15D
C18 C21 C22 C27 C33 C36 C40 C44 C47 C50 C56 C61 C71 C80 C84 C85 C97 C99 C100 C114 C119 C120 C126 C127 = C0603: CAP CER 0.1uF 50V X7R 0603; Manufacturer: Yageo; PN: CC0603KRX7R9BB104
C19 C20 C32 C38 C82 C96 = C0603: CAP CER 4.7UF 10V X7R 0603; Manufacturer: MURATA; PN: GRT21BR61H475KE13L
C23 C24 C39 = C0603: CAP CER 330pF 50V X7R 0603; Manufacturer: Yageo; PN: CC0603KRX7R9BB331
C25 C30 C31 C48 C66 C68 C74 C75 C89 C90 C108 C121-C123 = C0603: CAP CER 100pF 50V X7R 0603; Manufacturer: Yageo; PN: CC0603KRX7R9BB101
C26 C29 C37 C45 C49 C52 C60 C65 C69 C70 C73 C79 C88 C94 C104 C106 C109 C110 C129 = C0603: CAP CER 1uF 50V X7R 0603; Manufacturer: Yageo; PN: CC0603KRX7R9BB105
C28 C51 C72 = CAP NP: CAP CER 2.2UF 25V X7R 0603; Manufacturer: Murata; PN: GRM188Z71E225ME43D
C35 C41 = CE12.5: CAP ALUM POLY 220UF 20% 25V T/H; PN: RNU1E221MDNASQ
C42 C46 C124 C125 = C1206: CAP CER 10UF 25V X7R 1206; PN: CC1206KKX7R8BB106
C43 C86 C101 = C0603: CAP CER 2.2UF 25V X7R 0603; Manufacturer: Murata; PN: GRM188Z71E225ME43D
C53 C91 = CAP NP: CAP CER 1uF 50V X7R 0603; Manufacturer: Yageo; PN: CC0603KRX7R9BB105
C54 C103 C117 = C0603: CAP CER 220pF 50V NP0 0603; Manufacturer: Yageo; PN: CC0603KRNP09BB221
C57 C59 C62 C76 C78 C81 C92 C95 C98 C111 C113 C115 C128 = GRT21BR61H475KE13L: SMD/SMT 0805 50VDC 4.7uF 10% AEC-Q200; Manufacturer: Murata; Polarized: N; CompType: Capacitor; U/M: EA; Cap_F: 0.0000047; Tolerance_%: 10; VDC_V: 50; Value2: 50V; TempCo: X5R; TaMin_C: -55; TaMax_C: 85; Cap_Case: 0805; SizeArea_mm2: 2.5; SizeAreaWB_mm2: 6.75; SizeX_mm: 2; SizeY_mm: 1.25; SizeZ_mm: 1.45; AEC Category: Q200; AEC Qualified: Y; AEC Grade: 3; PN: GRT21BC71H475KE13L
C58 C63 C77 C83 C93 C102 C112 C116 = C0805: CAP CER 3300PF 100V NP0 0805; Manufacturer: KEMET; PN: C0805C332J1GAC7800
C64 C107 = C1206: CAP CER 10UF 35V X7R 1206; Manufacturer: TDK; PN: 7R1V106K160AE
C130 C131 C135-C137 = CAP NP_Dup1: CAP CER 0.47UF 1000V X7R 2220; Manufacturer: Murata; PN: KC355WD7LF474MH01
CN1 = CN2/3.81
CN2 = CP2*5/2.54
CN3 = CP5/2.54
D1 D2 = DIODE_0: DIODE SCHOTTKY 40V 1A SOD123FL; Manufacturer: Micro Commercia
D1_2 D3 = DIODE_0: DIODE SCHOTTKY 40V 1A SOD123FL; Manufacturer: Micro Commercia; PN: SL14PL-TP
D4 D5 D14 D15 D20 D21 = DIODE_0: DIODE GEN PURP 600V 1A SMB; Manufacturer: ON; PCB Footprint: SOD-123
D6 D8 = DIODE_0: DIODE SCHOTTKY 60V 1A SOD123; Manufacturer: Nexperia
D7 D11 D17 D23 = zener: DIODE ZENER 18.51V 500MW SOD323F; Manufacturer: Diodes; PN: DDZ20ASF-7
D9 D13 D19 D25 = CMP-004-00036-1: DIODE ZENER 3V 500MW SOD123; Manufacturer: Diodes; PN: BZT52C3V0-7-F
D10 D12 D16 D18 D22 D24 = DIODE_0: DIODE SCHOTTKY 60V 1A SOD123; Manufacturer: Nexperia; PCB Footprint: SOD-123
D26 D27 = DIODE_0: DIODE SCHOTTKY 200V 1A SOA; Manufacturer: Diodes Incorporated; PN: ES1D-13-F
J1 = 2*13P: CONN HDR 26POS 0.1 GOLD PCB 4PC; Manufacturer: Schmartboard; PN: 920-0134-01
J2 = 2*6P: RECEPTACLE STRIP 12P 2.54MM PITC; Manufacturer: Adam Tech; PN: RS2-12-G
L1 = LF-P9*6/L18*W9H1.0
NTC1 = VARISTOR: THERM NTC 10KOHM 3984K RING LUG; Manufacturer: Vishay; PCB Footprint: NTC_od20MM
Q1-Q6 = T2PAK_7L: U2 SIC MOSFET; Manufacturer: Wolfspeed
Q7-Q10 = SOT23-3: TRANS NPN 50V 1.25A SOT23-3; Manufacturer: Diodes; PN: FMMTL619TA
R1-R5 R9-R23 R32 R33 R43-R47 = R1206: RES SMD 620K OHM 1% 1/4W 1206; Manufacturer: Yageo; PN: RC1206FR-07620KL
R6-R8 R30 R31 R34 R61 R63-R65 R77 R78 = R0603: RES SMD 10K OHM 1% 1/10W 0603; Manufacturer: Yageo; PN: RC0603FR-0710KL
R24 R24_2 R25 R26 R74 R111 R118_2 R120 R120_2 = R1206: RES SMD 22 OHM 1% 1/4W 1206; Manufacturer: Yageo; PN: RC1206FR-0722RL
R27 = R1206: RES SMD 39R OHM 1% 1/4W 1206; Manufacturer: Yageo; PN: RC1206FR-0739RL
R27_2 R28 R29 R71 R109 R118 = R1206: RES SMD 39 OHM 1% 1/4W 1206; Manufacturer: Yageo; PN: RC1206FR-0739RL
R35-R37 R41 R42 R51 R57-R59 R73 R84 R85 R88 R140-R143 = R0603: RES SMD 0R OHM 1% 1/10W 0603; Manufacturer: Yageo; PN: RC0603FR-070RL
R38-R40 = R1206: RES SMD 330K OHM 1% 1/4W 1206; Manufacturer: Yageo; PN: RC1206FR-07330KL
R48-R50 R52 R53 R2512 = R: RES 0.002 OHM 1% 3W 2512; PN: LR2512-23R002F4
R54-R56 R68 R89 R102 = R1206: RES SMD 1 OHM 1% 1/4W 1206; Manufacturer: Yageo; PN: RC1206FR-071RL
R60 R62 R76 = R0603: RES SMD 33K OHM 1% 1/10W 0603; Manufacturer: Yageo; PN: RC0603FR-0733KL
R66 R81 R83 R99 R116 R127 = R0603: RES SMD 10 OHM 1% 1/10W 0603; Manufacturer: Yageo; PN: RC0603FR-0710RL
R67 R72 R80 R101 R110 R114 R119 R123 = R0603: RES SMD 100 OHM 1% 1/10W 0603; Manufacturer: Yageo; PN: RC0603FR-07100RL
R69 R75 R90 R94 R103 R112 R121 R124 R136 = R0603: RES SMD 4.7K OHM 1% 1/10W 0603; Manufacturer: Yageo; PN: RC0603FR-074K7L
R70 R108 R117 = R0603: RES SMD 4.9K OHM 1% 1/10W 0603; Manufacturer: Yageo; PN: RC0603FR-074K9L
R79 = R0805: RES SMD 0R OHM 1% 1/10W 0805; PN: RC0805FR-070RL
R86 = R1206: 'RES SMD 100 OHM 1% 1/4W 1206; Manufacturer: Yageo; PN: RC1206FR-07100RL
R93 R122 R135 = R0805: RES SMD 3K OHM 1% 1/8W 0805; Manufacturer1: Yageo; PN: RT0805FRE073KL
R95 R130 R139 = R0603: RES SMD 560 OHM 1% 1/10W 0603; Manufacturer: Yageo; PN: RC0603FR-07560RL
R96 R113 R125 R137 = R0603: RES SMD 2.7K OHM 1% 1/10W 0603; Manufacturer: Yageo; PN: RC0603FR-072K7L
R97 R107 R128 R134 = R: RES SMD 100K OHM 1% 1/10W 0603; Manufacturer: Yageo; PN: RC0603FR-07100KL
R98 = R: RES SMD 1K OHM 5% 1/2W 1206; Manufacturer: Yageo; PN: SR1206JR-7W1KL
R100 R129 = RESISTOR: RES SMD 3.24K OHM 1% 1/10W 0603; Manufacturer: Yageo; PN: RC0603FR-073K24L
R104 R132 = R0603: RES SMD 10K OHM 1% 1/10W 0603; Manufacturer: Yageo; PN: NC
R105 R131 = RESISTOR: RES SMD 97.6K OHM 1% 1/10W 0603; Manufacturer: Yageo; PN: RC0603FR-0797K6L
R106 R133 = RESISTOR: RES SMD 11K OHM 1% 1/10W 0603; Manufacturer: Yageo; PN: RC0603FR-0711KL
R115 R126 R138 = R0603: RES SMD 1K OHM 1% 1/10W 0603; Manufacturer: Yageo; PN: RC0603FR-071KL
R144 = R1206: RES SMD 0R OHM 1% 1/4W 1206; Manufacturer: Yageo; PN: RC1206FR-07620KL
RJ0 RJ1 = R1206: RES SMD 0 OHM 1% 1/4W 1206; Manufacturer: Yageo; PN: RC1206FR-070RL
T1-T4 = Trans_gate_1: XFRMR GATE DRIVE 1.41:1 SMD; Manufacturer: Wurth; PN: 750345425
U1 U3 U5 = SOIC16: 1MHZ BANDWIDTH INTEGRATED, HALL; Manufacturer: Allegro
U2 U7 U9 = UCC5350MC: 5A/5A, 5-KVRMS SINGLE-CHANNEL IS; Manufacturer: TI; PCB Footprint: SOIC8
U4 U10 U11 = CMP-00024-00019-3: Automotive ±10-A 5.7kV RMS single channel isolated gate driver for SiC/IGBT 16-SOIC -40 to 125; Manufacturer: TI
U8 U12 = UCC25800: 5A/5A, 3-KVRMS SINGLE-CHANNEL IS; Manufacturer: TI; PCB Footprint: SOIC8
U13 = AZ1117IH-3.3: AZ1117IH-3.3TRG1 SOT223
